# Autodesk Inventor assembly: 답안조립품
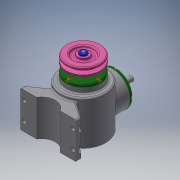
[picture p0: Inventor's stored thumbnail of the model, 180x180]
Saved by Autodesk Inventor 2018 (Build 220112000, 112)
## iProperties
Created: 2021-04
Part Number: 답안조립품
Document SubType Name: Assembly
Designer: theplan76
Author: theplan76
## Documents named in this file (17)
- C:\Users\theplan76\Desktop\710407V1018\답안조립품.iam
- C:\Users\theplan76\Desktop\710407V1018\부품1.ipt
- C:\Users\theplan76\Desktop\710407V1018\메인 축.ipt
- 메인 축.ipt
- C:\Users\theplan76\Desktop\710407V1018\키 4 x 4 x 14.ipt
- C:\Users\theplan76\Desktop\710407V1018\키 5 x 5 x 14.ipt
- C:\Users\theplan76\Desktop\710407V1018\메인 베벨기어.ipt
- C:\Users\theplan76\Desktop\710407V1018\베어링 6203.ipt
- C:\Users\theplan76\Desktop\710407V1018\커버.ipt
- C:\Users\theplan76\Desktop\710407V1018\오일실 17 x 32 x 8.ipt
- C:\Users\theplan76\Desktop\710407V1018\V-벨트풀리.ipt
- C:\Users\theplan76\Desktop\710407V1018\육각볼트 M4 x 8.ipt
- C:\Users\theplan76\Desktop\710407V1018\와셔 4 x 16.ipt
- C:\Users\theplan76\Desktop\710407V1018\서브 축.ipt
- 서브 축.ipt
- C:\Users\theplan76\Desktop\710407V1018\서브 베벨기어.ipt
- C:\Users\theplan76\Desktop\710407V1018\볼트 M4 x 10.ipt
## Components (1 placed, 1 different names)
1. V-벨트풀리:1
